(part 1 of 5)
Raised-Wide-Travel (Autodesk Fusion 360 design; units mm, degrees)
parameter "FrameLength" = 640 comment "Fixed existing outer length"
parameter "FrameWidth" = 190 comment "Fixed existing outer width"
parameter "FrameHeight" = 110 comment "Fixed existing height"
parameter "PivotHeight" = 30 comment "Above frame center"
parameter "LeverTravel" = 116 comment "Stable endpoint to endpoint"
parameter "PrintClearance" = 0.3 comment "Prototype diametral running clearance"
base_mesh_feature "Base Mesh Feature"
ground "Pin1"
work_plane "WorkPlane1" AlongDistance -36 ExtraOffset 0
sketch "Flat load-bearing plate" plane through (-36, 0, 0) normal (1, 0, 0) x axis (0, 0, -1)
  line L1 (-33, -55) -> (-33, -75)
  line L2 (2, -55) -> (-33, -55)
  line L3 (2, 55) -> (2, -55)
  line L4 (-33, 55) -> (2, 55)
  line L5 (-33, 75) -> (-33, 55)
  line L6 (-57, 75) -> (-33, 75)
  line L7 (-57, 32) -> (-57, 75)
  line L8 (-86, 26) -> (-57, 32)
  line L9 (-86, -26) -> (-86, 26)
  line L10 (-57, -32) -> (-86, -26)
  line L11 (-57, -75) -> (-57, -32)
  line L12 (-33, -75) -> (-57, -75)
extrude "Extrude1" new body sketch "Flat load-bearing plate" along normal blind 12
work_plane "WorkPlane2" AlongDistance -37 ExtraOffset 0
sketch "Replaceable bushing seat" plane through (-37, 0, 0) normal (1, 0, 0) x axis (0, 0, -1)
  circle C1 centre (-65, 0) radius 10.15
extrude "Extrude2" cut sketch "Replaceable bushing seat" along normal blind 14
work_plane "WorkPlane3" AlongDistance -37 ExtraOffset 0
sketch "Follower pivot bolt" plane through (-37, 0, 0) normal (1, 0, 0) x axis (0, 0, -1)
  circle C1 centre (-12, -35) radius 2.7
extrude "Extrude3" cut sketch "Follower pivot bolt" along normal blind 14
work_plane "WorkPlane4" AlongDistance -76 ExtraOffset 0
sketch "M5 rail mounting bore" plane through (0, -76, 0) normal (0, 1, 0) x axis (1, 0, 0)
  circle C1 centre (-30, -45) radius 2.7
extrude "Extrude4" cut sketch "M5 rail mounting bore" along normal blind 22
work_plane "WorkPlane5" AlongDistance -55 ExtraOffset 0
sketch "Rail screw tool and washer access" plane through (0, -55, 0) normal (0, 1, 0) x axis (1, 0, 0)
  circle C1 centre (-30, -45) radius 5.3
extrude "Extrude5" cut sketch "Rail screw tool and washer access" along normal blind 12
work_plane "WorkPlane6" AlongDistance 54 ExtraOffset 0
sketch "M5 rail mounting bore (1)" plane through (0, 54, 0) normal (0, 1, 0) x axis (1, 0, 0)
  circle C1 centre (-30, -45) radius 2.7
extrude "Extrude6" cut sketch "M5 rail mounting bore (1)" along normal blind 22
work_plane "WorkPlane7" AlongDistance 43 ExtraOffset 0
sketch "Rail screw tool and washer access (1)" plane through (0, 43, 0) normal (0, 1, 0) x axis (1, 0, 0)
  circle C1 centre (-30, -45) radius 5.3
extrude "Extrude7" cut sketch "Rail screw tool and washer access (1)" along normal blind 12
work_plane "WorkPlane8" AlongDistance -37 ExtraOffset 0
sketch "Spring crossblock attachment" plane through (-37, 0, 0) normal (1, 0, 0) x axis (0, 0, -1)
  circle C1 centre (-44, -59) radius 1.7
extrude "Extrude8" cut sketch "Spring crossblock attachment" along normal blind 14
work_plane "WorkPlane9" AlongDistance -37 ExtraOffset 0
sketch "Spring crossblock attachment (1)" plane through (-37, 0, 0) normal (1, 0, 0) x axis (0, 0, -1)
  circle C1 centre (-44, -51) radius 1.7
extrude "Extrude9" cut sketch "Spring crossblock attachment (1)" along normal blind 14
work_plane "WorkPlane1" AlongDistance 24 ExtraOffset 0
sketch "Flat load-bearing plate" plane through (24, 0, 0) normal (1, 0, 0) x axis (0, 0, -1)
  line L1 (-33, -55) -> (-33, -75)
  line L2 (2, -55) -> (-33, -55)
  line L3 (2, 55) -> (2, -55)
  line L4 (-33, 55) -> (2, 55)
  line L5 (-33, 75) -> (-33, 55)
  line L6 (-57, 75) -> (-33, 75)
  line L7 (-57, 32) -> (-57, 75)
  line L8 (-86, 26) -> (-57, 32)
  line L9 (-86, -26) -> (-86, 26)
  line L10 (-57, -32) -> (-86, -26)
  line L11 (-57, -75) -> (-57, -32)
  line L12 (-33, -75) -> (-57, -75)
extrude "Extrude1" new body sketch "Flat load-bearing plate" along normal blind 12
work_plane "WorkPlane2" AlongDistance 23 ExtraOffset 0
sketch "Replaceable bushing seat" plane through (23, 0, 0) normal (1, 0, 0) x axis (0, 0, -1)
  circle C1 centre (-65, 0) radius 10.15
extrude "Extrude2" cut sketch "Replaceable bushing seat" along normal blind 14
work_plane "WorkPlane3" AlongDistance 23 ExtraOffset 0
sketch "Follower pivot bolt" plane through (23, 0, 0) normal (1, 0, 0) x axis (0, 0, -1)
  circle C1 centre (-12, -35) radius 2.7
extrude "Extrude3" cut sketch "Follower pivot bolt" along normal blind 14
work_plane "WorkPlane4" AlongDistance -76 ExtraOffset 0
sketch "M5 rail mounting bore" plane through (0, -76, 0) normal (0, 1, 0) x axis (1, 0, 0)
  circle C1 centre (30, -45) radius 2.7
extrude "Extrude4" cut sketch "M5 rail mounting bore" along normal blind 22
work_plane "WorkPlane5" AlongDistance -55 ExtraOffset 0
sketch "Rail screw tool and washer access" plane through (0, -55, 0) normal (0, 1, 0) x axis (1, 0, 0)
  circle C1 centre (30, -45) radius 5.3
extrude "Extrude5" cut sketch "Rail screw tool and washer access" along normal blind 12
work_plane "WorkPlane6" AlongDistance 54 ExtraOffset 0
sketch "M5 rail mounting bore (1)" plane through (0, 54, 0) normal (0, 1, 0) x axis (1, 0, 0)
  circle C1 centre (30, -45) radius 2.7
extrude "Extrude6" cut sketch "M5 rail mounting bore (1)" along normal blind 22
work_plane "WorkPlane7" AlongDistance 43 ExtraOffset 0
sketch "Rail screw tool and washer access (1)" plane through (0, 43, 0) normal (0, 1, 0) x axis (1, 0, 0)
  circle C1 centre (30, -45) radius 5.3
extrude "Extrude7" cut sketch "Rail screw tool and washer access (1)" along normal blind 12
work_plane "WorkPlane8" AlongDistance 23 ExtraOffset 0
sketch "Spring crossblock attachment" plane through (23, 0, 0) normal (1, 0, 0) x axis (0, 0, -1)
  circle C1 centre (-44, -59) radius 1.7
extrude "Extrude8" cut sketch "Spring crossblock attachment" along normal blind 14
work_plane "WorkPlane9" AlongDistance 23 ExtraOffset 0
sketch "Spring crossblock attachment (1)" plane through (23, 0, 0) normal (1, 0, 0) x axis (0, 0, -1)
  circle C1 centre (-44, -51) radius 1.7
extrude "Extrude9" cut sketch "Spring crossblock attachment (1)" along normal blind 14
work_plane "WorkPlane1" AlongDistance -36 ExtraOffset 0
sketch "Replaceable journal body" plane through (-36, 0, 0) normal (1, 0, 0) x axis (0, 0, -1)
  circle C1 centre (-65, 0) radius 10.05
extrude "Extrude1" new body sketch "Replaceable journal body" along normal blind 12 bodies "P03 Left flanged journal bush"
work_plane "WorkPlane2" AlongDistance -37.2 ExtraOffset 0
sketch "Axial thrust flange" plane through (-37.2, 0, 0) normal (1, 0, 0) x axis (0, 0, -1)
  circle C1 centre (-65, 0) radius 12.75
extrude "Extrude2" add sketch "Axial thrust flange" along normal blind 1.2
work_plane "WorkPlane3" AlongDistance -38 ExtraOffset 0
sketch "Running journal bore" plane through (-38, 0, 0) normal (1, 0, 0) x axis (0, 0, -1)
  circle C1 centre (-65, 0) radius 6.15
extrude "Extrude3" cut sketch "Running journal bore" along normal blind 15
work_plane "WorkPlane1" AlongDistance 24 ExtraOffset 0
sketch "Replaceable journal body" plane through (24, 0, 0) normal (1, 0, 0) x axis (0, 0, -1)
  circle C1 centre (-65, 0) radius 10.05
extrude "Extrude1" new body sketch "Replaceable journal body" along normal blind 12 bodies "P04 Right flanged journal bush"
work_plane "WorkPlane2" AlongDistance 36 ExtraOffset 0
sketch "Axial thrust flange" plane through (36, 0, 0) normal (1, 0, 0) x axis (0, 0, -1)
  circle C1 centre (-65, 0) radius 12.75
extrude "Extrude2" add sketch "Axial thrust flange" along normal blind 1.2
work_plane "WorkPlane3" AlongDistance 23 ExtraOffset 0
sketch "Running journal bore" plane through (23, 0, 0) normal (1, 0, 0) x axis (0, 0, -1)
  circle C1 centre (-65, 0) radius 6.15
extrude "Extrude3" cut sketch "Running journal bore" along normal blind 15
work_plane "WorkPlane1" AlongDistance -39.35 ExtraOffset 0
sketch "Axial cap" plane through (-39.35, 0, 0) normal (1, 0, 0) x axis (0, 0, -1)
  circle C1 centre (-65, 0) radius 10
extrude "Extrude1" new body sketch "Axial cap" along normal blind 2 bodies "P06 Shaft retaining cap"
work_plane "WorkPlane2" AlongDistance -39.5 ExtraOffset 0
sketch "M3 cap screw" plane through (-39.5, 0, 0) normal (1, 0, 0) x axis (0, 0, -1)
  circle C1 centre (-65, 0) radius 1.7
extrude "Extrude2" cut sketch "M3 cap screw" along normal blind 2.4
work_plane "WorkPlane1" AlongDistance -7 ExtraOffset 0
sketch "Main lever hub" plane through (-7, 0, 0) normal (1, 0, 0) x axis (0, 0, -1)
  circle C1 centre (-65, 0) radius 22
extrude "Extrude1" new body sketch "Main lever hub" along normal blind 14 bodies "P07 Integral lever rotor and cam carrier"
work_plane "WorkPlane2" AlongDistance -7 ExtraOffset 0
sketch "Continuous reinforced lever stem" plane through (-7, 0, 0) normal (1, 0, 0) x axis (0, 0, -1)
  line L1 (-60, 14) -> (-60, -14)
  line L2 (-95, 11) -> (-60, 14)
  line L3 (-150, 7) -> (-95, 11)
  line L4 (-195, 7) -> (-150, 7)
  line L5 (-195, -7) -> (-195, 7)
  line L6 (-150, -7) -> (-195, -7)
  line L7 (-95, -11) -> (-150, -7)
  line L8 (-60, -14) -> (-95, -11)
extrude "Extrude2" add sketch "Continuous reinforced lever stem" along normal blind 14
work_plane "WorkPlane3" AlongDistance -7 ExtraOffset 0
sketch "Integrated cam carrier fan" plane through (-7, 0, 0) normal (1, 0, 0) x axis (0, 0, -1)
  line L1 (-44.5, 35.507) -> (-65, 0)
  line L2 (-42.6698, 34.3855) -> (-44.5, 35.507)
  line L3 (-40.9008, 33.1697) -> (-42.6698, 34.3855)
  line L4 (-39.1979, 31.863) -> (-40.9008, 33.1697)
  line L5 (-37.5656, 30.4689) -> (-39.1979, 31.863)
  line L6 (-36.0086, 28.9914) -> (-37.5656, 30.4689)
  line L7 (-34.5311, 27.4344) -> (-36.0086, 28.9914)
  line L8 (-33.137, 25.8021) -> (-34.5311, 27.4344)
  line L9 (-31.8303, 24.0992) -> (-33.137, 25.8021)
  line L10 (-30.6145, 22.3302) -> (-31.8303, 24.0992)
  line L11 (-29.493, 20.5) -> (-30.6145, 22.3302)
  line L12 (-28.4687, 18.6136) -> (-29.493, 20.5)
  line L13 (-27.5446, 16.6762) -> (-28.4687, 18.6136)
  line L14 (-26.7232, 14.6931) -> (-27.5446, 16.6762)
  line L15 (-26.0067, 12.6697) -> (-26.7232, 14.6931)
  line L16 (-25.397, 10.6116) -> (-26.0067, 12.6697)
  line L17 (-24.8959, 8.5244) -> (-25.397, 10.6116)
  line L18 (-24.5048, 6.4138) -> (-24.8959, 8.5244)
  line L19 (-24.2246, 4.2857) -> (-24.5048, 6.4138)
  line L20 (-24.0562, 2.1458) -> (-24.2246, 4.2857)
  line L21 (-24, 0) -> (-24.0562, 2.1458)
  line L22 (-24.0562, -2.1458) -> (-24, 0)
  line L23 (-24.2246, -4.2857) -> (-24.0562, -2.1458)
  line L24 (-24.5048, -6.4138) -> (-24.2246, -4.2857)
  line L25 (-24.8959, -8.5244) -> (-24.5048, -6.4138)
  line L26 (-25.397, -10.6116) -> (-24.8959, -8.5244)
  line L27 (-26.0067, -12.6697) -> (-25.397, -10.6116)
  line L28 (-26.7232, -14.6931) -> (-26.0067, -12.6697)
  line L29 (-27.5446, -16.6762) -> (-26.7232, -14.6931)
  line L30 (-28.4687, -18.6136) -> (-27.5446, -16.6762)
  line L31 (-29.493, -20.5) -> (-28.4687, -18.6136)
  line L32 (-30.6145, -22.3302) -> (-29.493, -20.5)
  line L33 (-31.8303, -24.0992) -> (-30.6145, -22.3302)
  line L34 (-33.137, -25.8021) -> (-31.8303, -24.0992)
  line L35 (-34.5311, -27.4344) -> (-33.137, -25.8021)
  line L36 (-36.0086, -28.9914) -> (-34.5311, -27.4344)
  line L37 (-37.5656, -30.4689) -> (-36.0086, -28.9914)
  line L38 (-39.1979, -31.863) -> (-37.5656, -30.4689)
  line L39 (-40.9008, -33.1697) -> (-39.1979, -31.863)
  line L40 (-42.6698, -34.3855) -> (-40.9008, -33.1697)
  line L41 (-44.5, -35.507) -> (-42.6698, -34.3855)
  line L42 (-65, 0) -> (-44.5, -35.507)
extrude "Extrude3" add sketch "Integrated cam carrier fan" along normal blind 14
work_plane "WorkPlane4" AlongDistance -23.6 ExtraOffset 0
sketch "Integral axial locating hub" plane through (-23.6, 0, 0) normal (1, 0, 0) x axis (0, 0, -1)
  circle C1 centre (-65, 0) radius 10
work_plane "WorkPlane5" AlongDistance -24 ExtraOffset 0
sketch "D shaft socket" plane through (-24, 0, 0) normal (1, 0, 0) x axis (0, 0, -1)
  line L1 (-69.6247, 6.65) -> (-60.3753, 6.65)
  arc A1 centre (-65, 0) radius 8.1 clockwise from (-60.3753, 6.65) to (-69.6247, 6.65)
extrude "Extrude5" cut sketch "D shaft socket" along normal blind 48
work_plane "WorkPlane6" AlongDistance 0.3 ExtraOffset 0
sketch "Cam M3 insert pocket" plane through (0.3, 0, 0) normal (1, 0, 0) x axis (0, 0, -1)
  circle C1 centre (-39.5442, 25.4558) radius 2
extrude "Extrude6" cut sketch "Cam M3 insert pocket" along normal blind 6.8
work_plane "WorkPlane7" AlongDistance 0.3 ExtraOffset 0
sketch "Cam M3 insert pocket (1)" plane through (0.3, 0, 0) normal (1, 0, 0) x axis (0, 0, -1)
  circle C1 centre (-29, 0) radius 2
extrude "Extrude7" cut sketch "Cam M3 insert pocket (1)" along normal blind 6.8
work_plane "WorkPlane8" AlongDistance 0.3 ExtraOffset 0
sketch "Cam M3 insert pocket (2)" plane through (0.3, 0, 0) normal (1, 0, 0) x axis (0, 0, -1)
  circle C1 centre (-39.5442, -25.4558) radius 2
extrude "Extrude8" cut sketch "Cam M3 insert pocket (2)" along normal blind 6.8
work_plane "WorkPlane9" AlongDistance -8 ExtraOffset 0
sketch "Grip through bolt" plane through (-8, 0, 0) normal (1, 0, 0) x axis (0, 0, -1)
  circle C1 centre (-180, 0) radius 1.7
extrude "Extrude9" cut sketch "Grip through bolt" along normal blind 16
work_plane "WorkPlane10" AlongDistance -8 ExtraOffset 0
sketch "Grip through bolt (1)" plane through (-8, 0, 0) normal (1, 0, 0) x axis (0, 0, -1)
  circle C1 centre (-190, 0) radius 1.7
extrude "Extrude10" cut sketch "Grip through bolt (1)" along normal blind 16
work_plane "WorkPlane1" AlongDistance 0 ExtraOffset 0
sketch "Palm grip smooth contour" plane through (0, 0, 0) normal (1, 0, 0) x axis (0, 0, -1)
  curve K1 (-225, 0) -> (-165, 12)
  line L1 (-225, 0) -> (-165, 0)
  line L2 (-165, 12) -> (-165, 0)
revolve "Revolve1" sketch "Palm grip smooth contour" AlongAngle 360 bodies "P09 Grip insert half"
work_plane "WorkPlane2" AlongDistance 0 ExtraOffset 0
sketch "Split on print bed face" plane through (0, 0, 0) normal (1, 0, 0) x axis (0, 0, -1)
  line L1 (-160, 30) -> (-160, -30)
  line L2 (-230, 30) -> (-160, 30)
  line L3 (-230, -30) -> (-230, 30)
  line L4 (-160, -30) -> (-230, -30)
extrude "Extrude1" cut sketch "Split on print bed face" along normal blind 30
work_plane "WorkPlane3" AlongDistance -7.2 ExtraOffset 0
sketch "Keyed stem socket" plane through (-7.2, 0, 0) normal (1, 0, 0) x axis (0, 0, -1)
  line L1 (-164, 7.2) -> (-164, -7.2)
  line L2 (-196, 7.2) -> (-164, 7.2)
  line L3 (-196, -7.2) -> (-196, 7.2)
  line L4 (-164, -7.2) -> (-196, -7.2)
extrude "Extrude2" cut sketch "Keyed stem socket" along normal blind 14.4
work_plane "WorkPlane4" AlongDistance -13.9 ExtraOffset 0
sketch "M3 grip heat set" plane through (-13.9, 0, 0) normal (1, 0, 0) x axis (0, 0, -1)
  circle C1 centre (-180, 0) radius 2
extrude "Extrude3" cut sketch "M3 grip heat set" along normal blind 6.8
work_plane "WorkPlane5" AlongDistance -13.9 ExtraOffset 0
sketch "M3 grip heat set (1)" plane through (-13.9, 0, 0) normal (1, 0, 0) x axis (0, 0, -1)
  circle C1 centre (-190, 0) radius 2
extrude "Extrude4" cut sketch "M3 grip heat set (1)" along normal blind 6.8
work_plane "WorkPlane1" AlongDistance 0 ExtraOffset 0
sketch "Palm grip smooth contour" plane through (0, 0, 0) normal (1, 0, 0) x axis (0, 0, -1)
  curve K1 (-225, 0) -> (-165, 12)
  line L1 (-225, 0) -> (-165, 0)
  line L2 (-165, 12) -> (-165, 0)
revolve "Revolve1" sketch "Palm grip smooth contour" AlongAngle 360 bodies "P10 Grip screw half"
work_plane "WorkPlane2" AlongDistance -30 ExtraOffset 0
sketch "Split on print bed face" plane through (-30, 0, 0) normal (1, 0, 0) x axis (0, 0, -1)
  line L1 (-160, 30) -> (-160, -30)
  line L2 (-230, 30) -> (-160, 30)
  line L3 (-230, -30) -> (-230, 30)
  line L4 (-160, -30) -> (-230, -30)
extrude "Extrude1" cut sketch "Split on print bed face" along normal blind 30
work_plane "WorkPlane3" AlongDistance -7.2 ExtraOffset 0
sketch "Keyed stem socket" plane through (-7.2, 0, 0) normal (1, 0, 0) x axis (0, 0, -1)
  line L1 (-164, 7.2) -> (-164, -7.2)
  line L2 (-196, 7.2) -> (-164, 7.2)
  line L3 (-196, -7.2) -> (-196, 7.2)
  line L4 (-164, -7.2) -> (-196, -7.2)
extrude "Extrude2" cut sketch "Keyed stem socket" along normal blind 14.4
work_plane "WorkPlane4" AlongDistance -0.1 ExtraOffset 0
sketch "Grip screw bore" plane through (-0.1, 0, 0) normal (1, 0, 0) x axis (0, 0, -1)
  circle C1 centre (-180, 0) radius 1.7
extrude "Extrude3" cut sketch "Grip screw bore" along normal blind 26
work_plane "WorkPlane5" AlongDistance 12.5 ExtraOffset 0
sketch "Recessed grip screw head" plane through (12.5, 0, 0) normal (1, 0, 0) x axis (0, 0, -1)
  circle C1 centre (-180, 0) radius 3.1
extrude "Extrude4" cut sketch "Recessed grip screw head" along normal blind 14
work_plane "WorkPlane6" AlongDistance -0.1 ExtraOffset 0
sketch "Grip screw bore (1)" plane through (-0.1, 0, 0) normal (1, 0, 0) x axis (0, 0, -1)
  circle C1 centre (-190, 0) radius 1.7
extrude "Extrude5" cut sketch "Grip screw bore (1)" along normal blind 26
work_plane "WorkPlane7" AlongDistance 12.5 ExtraOffset 0
sketch "Recessed grip screw head (1)" plane through (12.5, 0, 0) normal (1, 0, 0) x axis (0, 0, -1)
  circle C1 centre (-190, 0) radius 3.1
extrude "Extrude6" cut sketch "Recessed grip screw head (1)" along normal blind 14
work_plane "WorkPlane1" AlongDistance 4 ExtraOffset 0
sketch "First strong flat cheek" plane through (4, 0, 0) normal (1, 0, 0) x axis (0, 0, -1)
  line L1 (-6, -5) -> (-6, -61)
  line L2 (-7, 0) -> (-6, -5)
  line L3 (-17, 0) -> (-7, 0)
  line L4 (-18, -5) -> (-17, 0)
  line L5 (-18, -61) -> (-18, -5)
  line L6 (-6, -61) -> (-18, -61)
extrude "Extrude1" new body sketch "First strong flat cheek" along normal blind 3 bodies "P11 Forked roller follower"
work_plane "WorkPlane2" AlongDistance 4 ExtraOffset 0
sketch "Spring tail bridge" plane through (4, 0, 0) normal (1, 0, 0) x axis (0, 0, -1)
  line L1 (-6, -49) -> (-6, -61)
  line L2 (-18, -49) -> (-6, -49)
  line L3 (-18, -61) -> (-18, -49)
  line L4 (-6, -61) -> (-18, -61)
extrude "Extrude2" add sketch "Spring tail bridge" along normal blind 16
work_plane "WorkPlane3" AlongDistance 17 ExtraOffset 0
sketch "Second supporting cheek" plane through (17, 0, 0) normal (1, 0, 0) x axis (0, 0, -1)
  line L1 (-6, -5) -> (-6, -61)
  line L2 (-7, 0) -> (-6, -5)
  line L3 (-17, 0) -> (-7, 0)
  line L4 (-18, -5) -> (-17, 0)
  line L5 (-18, -61) -> (-18, -5)
  line L6 (-6, -61) -> (-18, -61)
extrude "Extrude3" add sketch "Second supporting cheek" along normal blind 3
work_plane "WorkPlane4" AlongDistance 4 ExtraOffset 0
sketch "Rounded roller cheek" plane through (4, 0, 0) normal (1, 0, 0) x axis (0, 0, -1)
  circle C1 centre (-12, 0) radius 6
extrude "Extrude4" add sketch "Rounded roller cheek" along normal blind 3
work_plane "WorkPlane5" AlongDistance 17 ExtraOffset 0
sketch "Rounded roller cheek (1)" plane through (17, 0, 0) normal (1, 0, 0) x axis (0, 0, -1)
  circle C1 centre (-12, 0) radius 6
extrude "Extrude5" add sketch "Rounded roller cheek (1)" along normal blind 3
work_plane "WorkPlane6" AlongDistance 3.9 ExtraOffset 0
sketch "Smooth pivot sleeve bore" plane through (3.9, 0, 0) normal (1, 0, 0) x axis (0, 0, -1)
  circle C1 centre (-12, -35) radius 4.15
extrude "Extrude6" cut sketch "Smooth pivot sleeve bore" along normal blind 16.2
work_plane "WorkPlane7" AlongDistance 3.9 ExtraOffset 0
sketch "Roller axle holes" plane through (3.9, 0, 0) normal (1, 0, 0) x axis (0, 0, -1)
  circle C1 centre (-12, 0) radius 1.7
extrude "Extrude7" cut sketch "Roller axle holes" along normal blind 16.2
work_plane "WorkPlane8" AlongDistance 3.9 ExtraOffset 0
sketch "Roller M3 nut recess" plane through (3.9, 0, 0) normal (1, 0, 0) x axis (0, 0, -1)
  line L1 (-14.9, 1.6743) -> (-12, 3.3486)
  line L2 (-14.9, -1.6743) -> (-14.9, 1.6743)
  line L3 (-12, -3.3486) -> (-14.9, -1.6743)
  line L4 (-9.1, -1.6743) -> (-12, -3.3486)
  line L5 (-9.1, 1.6743) -> (-9.1, -1.6743)
  line L6 (-12, 3.3486) -> (-9.1, 1.6743)
extrude "Extrude8" cut sketch "Roller M3 nut recess" along normal blind 1.6
work_plane "WorkPlane9" AlongDistance 18 ExtraOffset 0
sketch "Spring tail locating pilot" plane through (0, 0, 18) normal (0, 0, 1) x axis (1, 0, 0)
  circle C1 centre (12, -55) radius 1.8
extrude "Extrude9" add sketch "Spring tail locating pilot" along normal blind 2
work_plane "WorkPlane1" AlongDistance -24 ExtraOffset 0
sketch "Captured spring reaction block" plane through (-24, 0, 0) normal (1, 0, 0) x axis (0, 0, -1)
  line L1 (-38, -44) -> (-38, -66)
  line L2 (-52, -44) -> (-38, -44)
  line L3 (-52, -66) -> (-52, -44)
  line L4 (-38, -66) -> (-52, -66)
extrude "Extrude1" new body sketch "Captured spring reaction block" along normal blind 48
work_plane "WorkPlane2" AlongDistance -24.1 ExtraOffset 0
sketch "Left M3 insert with screw tip relief" plane through (-24.1, 0, 0) normal (1, 0, 0) x axis (0, 0, -1)
  circle C1 centre (-44, -59) radius 2
extrude "Extrude2" cut sketch "Left M3 insert with screw tip relief" along normal blind 8.8
work_plane "WorkPlane3" AlongDistance 15.3 ExtraOffset 0
sketch "Right M3 insert with screw tip relief" plane through (15.3, 0, 0) normal (1, 0, 0) x axis (0, 0, -1)
  circle C1 centre (-44, -59) radius 2
extrude "Extrude3" cut sketch "Right M3 insert with screw tip relief" along normal blind 8.8
work_plane "WorkPlane4" AlongDistance -24.1 ExtraOffset 0
sketch "Left M3 insert with screw tip relief (1)" plane through (-24.1, 0, 0) normal (1, 0, 0) x axis (0, 0, -1)
  circle C1 centre (-44, -51) radius 2
extrude "Extrude4" cut sketch "Left M3 insert with screw tip relief (1)" along normal blind 8.8
work_plane "WorkPlane5" AlongDistance 15.3 ExtraOffset 0
sketch "Right M3 insert with screw tip relief (1)" plane through (15.3, 0, 0) normal (1, 0, 0) x axis (0, 0, -1)
  circle C1 centre (-44, -51) radius 2
extrude "Extrude5" cut sketch "Right M3 insert with screw tip relief (1)" along normal blind 8.8
work_plane "WorkPlane6" AlongDistance 37.9 ExtraOffset 0
sketch "M4 preload adjuster" plane through (0, 0, 37.9) normal (0, 0, 1) x axis (1, 0, 0)
  circle C1 centre (12, -55) radius 2.2
extrude "Extrude6" cut sketch "M4 preload adjuster" along normal blind 14.2
work_plane "WorkPlane7" AlongDistance 37.9 ExtraOffset 0
sketch "Spring-side loaded retained M4 nut" plane through (0, 0, 37.9) normal (0, 0, 1) x axis (1, 0, 0)
  line L1 (14.1362, -51.3) -> (16.2724, -55)
  line L2 (9.8638, -51.3) -> (14.1362, -51.3)
  line L3 (7.7276, -55) -> (9.8638, -51.3)
  line L4 (9.8638, -58.7) -> (7.7276, -55)
  line L5 (14.1362, -58.7) -> (9.8638, -58.7)
  line L6 (16.2724, -55) -> (14.1362, -58.7)
extrude "Extrude7" cut sketch "Spring-side loaded retained M4 nut" along normal blind 3.5
work_plane "WorkPlane8" AlongDistance 37.9 ExtraOffset 0
sketch "Spring cup guide bolts" plane through (0, 0, 37.9) normal (0, 0, 1) x axis (1, 0, 0)
  circle C1 centre (5, -55) radius 1.7
extrude "Extrude8" cut sketch "Spring cup guide bolts" along normal blind 14.2
work_plane "WorkPlane9" AlongDistance 37.9 ExtraOffset 0
sketch "Spring cup guide bolts (1)" plane through (0, 0, 37.9) normal (0, 0, 1) x axis (1, 0, 0)
  circle C1 centre (19, -55) radius 1.7
extrude "Extrude9" cut sketch "Spring cup guide bolts (1)" along normal blind 14.2
work_plane "WorkPlane11" AlongDistance -18 ExtraOffset 0
sketch "Dedicated thick stop lug" plane through (-18, 0, 0) normal (1, 0, 0) x axis (0, 0, -1)
  line L1 (-72, 5) -> (-72, -5)
  line L2 (-95, 5) -> (-72, 5)
  line L3 (-95, -5) -> (-95, 5)
  line L4 (-72, -5) -> (-95, -5)
extrude "Extrude11" add sketch "Dedicated thick stop lug" along normal blind 11.5
work_plane "WorkPlane12" AlongDistance -18 ExtraOffset 0
sketch "Rounded stop contact" plane through (-18, 0, 0) normal (1, 0, 0) x axis (0, 0, -1)
  circle C1 centre (-95, 0) radius 5
extrude "Extrude12" add sketch "Rounded stop contact" along normal blind 11.5
work_plane "WorkPlane10" AlongDistance -36 ExtraOffset 0
sketch "Broad stop support ear" plane through (-36, 0, 0) normal (1, 0, 0) x axis (0, 0, -1)
  line L1 (-60, -20) -> (-60, -44)
  line L2 (-90, -20) -> (-60, -20)
  line L3 (-90, -44) -> (-90, -20)
  line L4 (-60, -44) -> (-90, -44)
extrude "Extrude10" add sketch "Broad stop support ear" along normal blind 12
work_plane "WorkPlane11" AlongDistance -24 ExtraOffset 0
sketch "Integrated steel-core end stop" plane through (-24, 0, 0) normal (1, 0, 0) x axis (0, 0, -1)
  circle C1 centre (-79.6754, -33.9652) radius 6
work_plane "WorkPlane12" AlongDistance -36.1 ExtraOffset 0
sketch "M5 stop reinforcement bolt" plane through (-36.1, 0, 0) normal (1, 0, 0) x axis (0, 0, -1)
  circle C1 centre (-79.6754, -33.9652) radius 2.7
work_plane "WorkPlane13" AlongDistance -15.4 ExtraOffset 0
sketch "M5 captive stop nut" plane through (-15.4, 0, 0) normal (1, 0, 0) x axis (0, 0, -1)
  line L1 (-83.8754, -31.5403) -> (-79.6754, -29.1154)
  line L2 (-83.8754, -36.39) -> (-83.8754, -31.5403)
  line L3 (-79.6754, -38.8149) -> (-83.8754, -36.39)
  line L4 (-75.4754, -36.39) -> (-79.6754, -38.8149)
  line L5 (-75.4754, -31.5403) -> (-75.4754, -36.39)
  line L6 (-79.6754, -29.1154) -> (-75.4754, -31.5403)
work_plane "WorkPlane14" AlongDistance -36 ExtraOffset 0
sketch "Broad stop support ear (1)" plane through (-36, 0, 0) normal (1, 0, 0) x axis (0, 0, -1)
  line L1 (-60, 44) -> (-60, 20)
  line L2 (-90, 44) -> (-60, 44)
  line L3 (-90, 20) -> (-90, 44)
  line L4 (-60, 20) -> (-90, 20)
extrude "Extrude14" add sketch "Broad stop support ear (1)" along normal blind 12
work_plane "WorkPlane15" AlongDistance -24 ExtraOffset 0
sketch "Integrated steel-core end stop (1)" plane through (-24, 0, 0) normal (1, 0, 0) x axis (0, 0, -1)
  circle C1 centre (-79.6754, 33.9652) radius 6
work_plane "WorkPlane16" AlongDistance -36.1 ExtraOffset 0
sketch "M5 stop reinforcement bolt (1)" plane through (-36.1, 0, 0) normal (1, 0, 0) x axis (0, 0, -1)
  circle C1 centre (-79.6754, 33.9652) radius 2.7
work_plane "WorkPlane17" AlongDistance -15.4 ExtraOffset 0
sketch "M5 captive stop nut (1)" plane through (-15.4, 0, 0) normal (1, 0, 0) x axis (0, 0, -1)
  line L1 (-83.8754, 36.39) -> (-79.6754, 38.8149)
  line L2 (-83.8754, 31.5403) -> (-83.8754, 36.39)
  line L3 (-79.6754, 29.1154) -> (-83.8754, 31.5403)
  line L4 (-75.4754, 31.5403) -> (-79.6754, 29.1154)
  line L5 (-75.4754, 36.39) -> (-75.4754, 31.5403)
  line L6 (-79.6754, 38.8149) -> (-75.4754, 36.39)
work_plane "WorkPlane13" AlongDistance -24 ExtraOffset 0
sketch "Restore shaft socket through stop-lug root" plane through (-24, 0, 0) normal (1, 0, 0) x axis (0, 0, -1)
  line L1 (-69.6247, 6.65) -> (-60.3753, 6.65)
  arc A1 centre (-65, 0) radius 8.1 clockwise from (-60.3753, 6.65) to (-69.6247, 6.65)
extrude "Extrude13" cut sketch "Restore shaft socket through stop-lug root" along normal blind 48
work_plane "WorkPlane10" AlongDistance -24.1 ExtraOffset 0
sketch "Cam sweep clearance through crossblock" plane through (-24.1, 0, 0) normal (1, 0, 0) x axis (0, 0, -1)
  circle C1 centre (-65, 0) radius 51
extrude "Extrude10" cut sketch "Cam sweep clearance through crossblock" along normal blind 48.2
work_plane "WorkPlane10" AlongDistance 36 ExtraOffset 0
sketch "Rigid sensor carriage support" plane through (36, 0, 0) normal (1, 0, 0) x axis (0, 0, -1)
  line L1 (-49, -18) -> (-49, -28)
  line L2 (-81, -18) -> (-49, -18)
  line L3 (-81, -28) -> (-81, -18)
  line L4 (-49, -28) -> (-81, -28)
extrude "Extrude10" add sketch "Rigid sensor carriage support" along normal blind 44
work_plane "WorkPlane11" AlongDistance -28.1 ExtraOffset 0
sketch "M3 sensor carriage heat set" plane through (0, -28.1, 0) normal (0, 1, 0) x axis (1, 0, 0)
  circle C1 centre (74, -65) radius 2
extrude "Extrude11" cut sketch "M3 sensor carriage heat set" along normal blind 6.8
work_plane "WorkPlane12" AlongDistance 36 ExtraOffset 0
sketch "Rigid sensor carriage support (1)" plane through (36, 0, 0) normal (1, 0, 0) x axis (0, 0, -1)
  line L1 (-49, 28) -> (-49, 18)
  line L2 (-81, 28) -> (-49, 28)
  line L3 (-81, 18) -> (-81, 28)
  line L4 (-49, 18) -> (-81, 18)
extrude "Extrude12" add sketch "Rigid sensor carriage support (1)" along normal blind 44
work_plane "WorkPlane13" AlongDistance 21.3 ExtraOffset 0
sketch "M3 sensor carriage heat set (1)" plane through (0, 21.3, 0) normal (0, 1, 0) x axis (1, 0, 0)
  circle C1 centre (74, -65) radius 2
extrude "Extrude13" cut sketch "M3 sensor carriage heat set (1)" along normal blind 6.8
work_plane "WorkPlane1" AlongDistance -24 ExtraOffset 0
sketch "Controlled follower end float" plane through (-24, 0, 0) normal (1, 0, 0) x axis (0, 0, -1)
  circle C1 centre (-12, -35) radius 6
extrude "Extrude1" new body sketch "Controlled follower end float" along normal blind 27.8 bodies "P21 Follower left axial spacer"
work_plane "WorkPlane2" AlongDistance -24.1 ExtraOffset 0
sketch "Pivot sleeve running clearance" plane through (-24.1, 0, 0) normal (1, 0, 0) x axis (0, 0, -1)
  circle C1 centre (-12, -35) radius 4.2
extrude "Extrude2" cut sketch "Pivot sleeve running clearance" along normal blind 28
work_plane "WorkPlane1" AlongDistance 20.2 ExtraOffset 0
sketch "Controlled follower end float" plane through (20.2, 0, 0) normal (1, 0, 0) x axis (0, 0, -1)
  circle C1 centre (-12, -35) radius 6
extrude "Extrude1" new body sketch "Controlled follower end float" along normal blind 3.8 bodies "P22 Follower right axial spacer"
work_plane "WorkPlane2" AlongDistance 20.1 ExtraOffset 0
sketch "Pivot sleeve running clearance" plane through (20.1, 0, 0) normal (1, 0, 0) x axis (0, 0, -1)
  circle C1 centre (-12, -35) radius 4.2
extrude "Extrude2" cut sketch "Pivot sleeve running clearance" along normal blind 4
work_plane "WorkPlane1" AlongDistance 3.1 ExtraOffset 0
sketch "Roller axle M3 nut" plane through (3.1, 0, 0) normal (1, 0, 0) x axis (0, 0, -1)
  line L1 (-14.75, 1.5877) -> (-12, 3.1754)
  line L2 (-14.75, -1.5877) -> (-14.75, 1.5877)
  line L3 (-12, -3.1754) -> (-14.75, -1.5877)
  line L4 (-9.25, -1.5877) -> (-12, -3.1754)
  line L5 (-9.25, 1.5877) -> (-9.25, -1.5877)
  line L6 (-12, 3.1754) -> (-9.25, 1.5877)
extrude "Extrude1" new body sketch "Roller axle M3 nut" along normal blind 2.4 bodies "HARDWARE Roller axle M3 nut"
work_plane "WorkPlane2" AlongDistance 3 ExtraOffset 0
sketch "Thread envelope" plane through (3, 0, 0) normal (1, 0, 0) x axis (0, 0, -1)
  circle C1 centre (-12, 0) radius 1.5
extrude "Extrude2" cut sketch "Thread envelope" along normal blind 2.6
work_plane "WorkPlane14" AlongDistance 23.9 ExtraOffset 0
sketch "Cam lateral service opening" plane through (23.9, 0, 0) normal (1, 0, 0) x axis (0, 0, -1)
  line L1 (-42.2047, 46.7373) -> (-43.8497, 47.5044)
  line L2 (-40.5875, 45.9133) -> (-42.2047, 46.7373)
  line L3 (-39, 45.0333) -> (-40.5875, 45.9133)
  line L4 (-37.4442, 44.0985) -> (-39, 45.0333)
  line L5 (-35.922, 43.11) -> (-37.4442, 44.0985)
  line L6 (-34.4352, 42.0689) -> (-35.922, 43.11)
  line L7 (-32.9856, 40.9766) -> (-34.4352, 42.0689)
  line L8 (-31.575, 39.8343) -> (-32.9856, 40.9766)
  line L9 (-30.2052, 38.6435) -> (-31.575, 39.8343)
  line L10 (-28.8778, 37.4057) -> (-30.2052, 38.6435)
  line L11 (-27.5943, 36.1222) -> (-28.8778, 37.4057)
  line L12 (-26.3565, 34.7948) -> (-27.5943, 36.1222)
  line L13 (-25.1657, 33.425) -> (-26.3565, 34.7948)
  line L14 (-24.0234, 32.0144) -> (-25.1657, 33.425)
  line L15 (-22.9311, 30.5648) -> (-24.0234, 32.0144)
  line L16 (-21.89, 29.078) -> (-22.9311, 30.5648)
  line L17 (-20.9015, 27.5558) -> (-21.89, 29.078)
  line L18 (-19.9667, 26) -> (-20.9015, 27.5558)
  line L19 (-19.0867, 24.4125) -> (-19.9667, 26)
  line L20 (-18.2627, 22.7953) -> (-19.0867, 24.4125)
  line L21 (-17.4956, 21.1503) -> (-18.2627, 22.7953)
  line L22 (-16.7864, 19.4795) -> (-17.4956, 21.1503)
  line L23 (-16.136, 17.785) -> (-16.7864, 19.4795)
  line L24 (-15.5451, 16.0689) -> (-16.136, 17.785)
  line L25 (-15.0144, 14.3331) -> (-15.5451, 16.0689)
  line L26 (-14.5446, 12.5799) -> (-15.0144, 14.3331)
  line L27 (-14.1363, 10.8114) -> (-14.5446, 12.5799)
  line L28 (-13.79, 9.0297) -> (-14.1363, 10.8114)
  line L29 (-13.5061, 7.237) -> (-13.79, 9.0297)
  line L30 (-13.2849, 5.4355) -> (-13.5061, 7.237)
  line L31 (-13.1267, 3.6273) -> (-13.2849, 5.4355)
  line L32 (-13.0317, 1.8148) -> (-13.1267, 3.6273)
  line L33 (-13, 0) -> (-13.0317, 1.8148)
  line L34 (-13.0317, -1.8148) -> (-13, 0)
  line L35 (-13.1267, -3.6273) -> (-13.0317, -1.8148)
  line L36 (-13.2849, -5.4355) -> (-13.1267, -3.6273)
  line L37 (-13.5061, -7.237) -> (-13.2849, -5.4355)
  line L38 (-13.79, -9.0297) -> (-13.5061, -7.237)
  line L39 (-14.1363, -10.8114) -> (-13.79, -9.0297)
  line L40 (-14.5446, -12.5799) -> (-14.1363, -10.8114)
  line L41 (-15.0144, -14.3331) -> (-14.5446, -12.5799)
  line L42 (-15.5451, -16.0689) -> (-15.0144, -14.3331)
  line L43 (-16.136, -17.785) -> (-15.5451, -16.0689)
  line L44 (-16.7864, -19.4795) -> (-16.136, -17.785)
  line L45 (-17.4956, -21.1503) -> (-16.7864, -19.4795)
  line L46 (-18.2627, -22.7953) -> (-17.4956, -21.1503)
  line L47 (-19.0867, -24.4125) -> (-18.2627, -22.7953)
  line L48 (-19.9667, -26) -> (-19.0867, -24.4125)
  line L49 (-20.9015, -27.5558) -> (-19.9667, -26)
  line L50 (-21.89, -29.078) -> (-20.9015, -27.5558)
  line L51 (-22.9311, -30.5648) -> (-21.89, -29.078)
  line L52 (-24.0234, -32.0144) -> (-22.9311, -30.5648)
  line L53 (-25.1657, -33.425) -> (-24.0234, -32.0144)
  line L54 (-26.3565, -34.7948) -> (-25.1657, -33.425)
  line L55 (-27.5943, -36.1222) -> (-26.3565, -34.7948)
  line L56 (-28.8778, -37.4057) -> (-27.5943, -36.1222)
  line L57 (-30.2052, -38.6435) -> (-28.8778, -37.4057)
  line L58 (-31.575, -39.8343) -> (-30.2052, -38.6435)
  line L59 (-32.9856, -40.9766) -> (-31.575, -39.8343)
  line L60 (-34.4352, -42.0689) -> (-32.9856, -40.9766)
  line L61 (-35.922, -43.11) -> (-34.4352, -42.0689)
  line L62 (-37.4442, -44.0985) -> (-35.922, -43.11)
  line L63 (-39, -45.0333) -> (-37.4442, -44.0985)
  line L64 (-40.5875, -45.9133) -> (-39, -45.0333)
  line L65 (-42.2047, -46.7373) -> (-40.5875, -45.9133)
  line L66 (-43.8497, -47.5044) -> (-42.2047, -46.7373)
  line L67 (-54.4248, -23.7522) -> (-43.8497, -47.5044)
  line L68 (-53.6024, -23.3686) -> (-54.4248, -23.7522)
  line L69 (-52.7937, -22.9566) -> (-53.6024, -23.3686)
  line L70 (-52, -22.5167) -> (-52.7937, -22.9566)
  line L71 (-51.2221, -22.0493) -> (-52, -22.5167)
  line L72 (-50.461, -21.555) -> (-51.2221, -22.0493)
  line L73 (-49.7176, -21.0344) -> (-50.461, -21.555)
  line L74 (-48.9928, -20.4883) -> (-49.7176, -21.0344)
  line L75 (-48.2875, -19.9172) -> (-48.9928, -20.4883)
  line L76 (-47.6026, -19.3218) -> (-48.2875, -19.9172)
  line L77 (-46.9389, -18.7028) -> (-47.6026, -19.3218)
  line L78 (-46.2972, -18.0611) -> (-46.9389, -18.7028)
  line L79 (-45.6782, -17.3974) -> (-46.2972, -18.0611)
  line L80 (-45.0828, -16.7125) -> (-45.6782, -17.3974)
  line L81 (-44.5117, -16.0072) -> (-45.0828, -16.7125)
  line L82 (-43.9656, -15.2824) -> (-44.5117, -16.0072)
  line L83 (-43.445, -14.539) -> (-43.9656, -15.2824)
  line L84 (-42.9507, -13.7779) -> (-43.445, -14.539)
  line L85 (-42.4833, -13) -> (-42.9507, -13.7779)
  line L86 (-42.0434, -12.2063) -> (-42.4833, -13)
  line L87 (-41.6314, -11.3976) -> (-42.0434, -12.2063)
  line L88 (-41.2478, -10.5752) -> (-41.6314, -11.3976)
  line L89 (-40.8932, -9.7398) -> (-41.2478, -10.5752)
  line L90 (-40.568, -8.8925) -> (-40.8932, -9.7398)
  line L91 (-40.2725, -8.0344) -> (-40.568, -8.8925)
  line L92 (-40.0072, -7.1666) -> (-40.2725, -8.0344)
  line L93 (-39.7723, -6.29) -> (-40.0072, -7.1666)
  line L94 (-39.5682, -5.4057) -> (-39.7723, -6.29)
  line L95 (-39.395, -4.5149) -> (-39.5682, -5.4057)
  line L96 (-39.253, -3.6185) -> (-39.395, -4.5149)
  line L97 (-39.1424, -2.7177) -> (-39.253, -3.6185)
  line L98 (-39.0633, -1.8137) -> (-39.1424, -2.7177)
  line L99 (-39.0158, -0.9074) -> (-39.0633, -1.8137)
  line L100 (-39, 0) -> (-39.0158, -0.9074)
  line L101 (-39.0158, 0.9074) -> (-39, 0)
  line L102 (-39.0633, 1.8137) -> (-39.0158, 0.9074)
  line L103 (-39.1424, 2.7177) -> (-39.0633, 1.8137)
  line L104 (-39.253, 3.6185) -> (-39.1424, 2.7177)
  line L105 (-39.395, 4.5149) -> (-39.253, 3.6185)
  line L106 (-39.5682, 5.4057) -> (-39.395, 4.5149)
  line L107 (-39.7723, 6.29) -> (-39.5682, 5.4057)
  line L108 (-40.0072, 7.1666) -> (-39.7723, 6.29)
  line L109 (-40.2725, 8.0344) -> (-40.0072, 7.1666)
  line L110 (-40.568, 8.8925) -> (-40.2725, 8.0344)
  line L111 (-40.8932, 9.7398) -> (-40.568, 8.8925)
  line L112 (-41.2478, 10.5752) -> (-40.8932, 9.7398)
  line L113 (-41.6314, 11.3976) -> (-41.2478, 10.5752)
  line L114 (-42.0434, 12.2063) -> (-41.6314, 11.3976)
  line L115 (-42.4833, 13) -> (-42.0434, 12.2063)
  line L116 (-42.9507, 13.7779) -> (-42.4833, 13)
  line L117 (-43.445, 14.539) -> (-42.9507, 13.7779)
  line L118 (-43.9656, 15.2824) -> (-43.445, 14.539)
  line L119 (-44.5117, 16.0072) -> (-43.9656, 15.2824)
  line L120 (-45.0828, 16.7125) -> (-44.5117, 16.0072)
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extrude "Extrude14" cut sketch "Cam lateral service opening" along normal blind 12.2
work_plane "WorkPlane15" AlongDistance 36 ExtraOffset 0
sketch "Clear service path beneath sensor rails" plane through (36, 0, 0) normal (1, 0, 0) x axis (0, 0, -1)
  line L1 (-48.9, -18) -> (-48.9, -28)
  line L2 (-56, -18) -> (-48.9, -18)
  line L3 (-56, -28) -> (-56, -18)
  line L4 (-48.9, -28) -> (-56, -28)
extrude "Extrude15" cut sketch "Clear service path beneath sensor rails" along normal blind 44.1
work_plane "WorkPlane16" AlongDistance 36 ExtraOffset 0
sketch "Clear service path beneath sensor rails (1)" plane through (36, 0, 0) normal (1, 0, 0) x axis (0, 0, -1)
  line L1 (-48.9, 28) -> (-48.9, 18)
  line L2 (-56, 28) -> (-48.9, 28)
  line L3 (-56, 18) -> (-56, 28)
  line L4 (-48.9, 18) -> (-56, 18)
extrude "Extrude16" cut sketch "Clear service path beneath sensor rails (1)" along normal blind 44.1
work_plane "WorkPlane11" AlongDistance -24 ExtraOffset 0
sketch "Raise mount clear of rail bolt axes" plane through (-24, 0, 0) normal (1, 0, 0) x axis (0, 0, -1)
  line L1 (-52, -44) -> (-52, -66)
  line L2 (-57, -44) -> (-52, -44)
  line L3 (-57, -66) -> (-57, -44)
  line L4 (-52, -66) -> (-57, -66)
extrude "Extrude11" add sketch "Raise mount clear of rail bolt axes" along normal blind 48
work_plane "WorkPlane12" AlongDistance -24 ExtraOffset 0
sketch "Close old block mounting hole" plane through (-24, 0, 0) normal (1, 0, 0) x axis (0, 0, -1)
  circle C1 centre (-44, -59) radius 2.01
extrude "Extrude12" add sketch "Close old block mounting hole" along normal blind 8.7
work_plane "WorkPlane13" AlongDistance -24.1 ExtraOffset 0
sketch "Raised M3 block insert" plane through (-24.1, 0, 0) normal (1, 0, 0) x axis (0, 0, -1)
  circle C1 centre (-52, -59) radius 2
extrude "Extrude13" cut sketch "Raised M3 block insert" along normal blind 8.9
work_plane "WorkPlane14" AlongDistance 15.3 ExtraOffset 0
sketch "Close old block mounting hole (1)" plane through (15.3, 0, 0) normal (1, 0, 0) x axis (0, 0, -1)
  circle C1 centre (-44, -59) radius 2.01
extrude "Extrude14" add sketch "Close old block mounting hole (1)" along normal blind 8.7
work_plane "WorkPlane15" AlongDistance 15.2 ExtraOffset 0
sketch "Raised M3 block insert (1)" plane through (15.2, 0, 0) normal (1, 0, 0) x axis (0, 0, -1)
  circle C1 centre (-52, -59) radius 2
extrude "Extrude15" cut sketch "Raised M3 block insert (1)" along normal blind 8.9
work_plane "WorkPlane18" AlongDistance -36 ExtraOffset 0
sketch "Close old plate mounting hole" plane through (-36, 0, 0) normal (1, 0, 0) x axis (0, 0, -1)
  circle C1 centre (-44, -59) radius 1.71
extrude "Extrude18" add sketch "Close old plate mounting hole" along normal blind 12
work_plane "WorkPlane19" AlongDistance -36.1 ExtraOffset 0
sketch "Raised M3 block fastener" plane through (-36.1, 0, 0) normal (1, 0, 0) x axis (0, 0, -1)
  circle C1 centre (-52, -59) radius 1.7
extrude "Extrude19" cut sketch "Raised M3 block fastener" along normal blind 12.2
work_plane "WorkPlane17" AlongDistance 24 ExtraOffset 0
sketch "Close old plate mounting hole" plane through (24, 0, 0) normal (1, 0, 0) x axis (0, 0, -1)
  circle C1 centre (-44, -59) radius 1.71
extrude "Extrude17" add sketch "Close old plate mounting hole" along normal blind 12
work_plane "WorkPlane18" AlongDistance 23.9 ExtraOffset 0
sketch "Raised M3 block fastener" plane through (23.9, 0, 0) normal (1, 0, 0) x axis (0, 0, -1)
  circle C1 centre (-52, -59) radius 1.7
extrude "Extrude18" cut sketch "Raised M3 block fastener" along normal blind 12.2
work_plane "WorkPlane16" AlongDistance -24 ExtraOffset 0
sketch "Close old block mounting hole (2)" plane through (-24, 0, 0) normal (1, 0, 0) x axis (0, 0, -1)
  circle C1 centre (-44, -51) radius 2.01
extrude "Extrude16" add sketch "Close old block mounting hole (2)" along normal blind 8.7
work_plane "WorkPlane17" AlongDistance -24.1 ExtraOffset 0
sketch "Raised M3 block insert (2)" plane through (-24.1, 0, 0) normal (1, 0, 0) x axis (0, 0, -1)
  circle C1 centre (-52, -51) radius 2
extrude "Extrude17" cut sketch "Raised M3 block insert (2)" along normal blind 8.9
work_plane "WorkPlane18" AlongDistance 15.3 ExtraOffset 0
sketch "Close old block mounting hole (3)" plane through (15.3, 0, 0) normal (1, 0, 0) x axis (0, 0, -1)
  circle C1 centre (-44, -51) radius 2.01
extrude "Extrude18" add sketch "Close old block mounting hole (3)" along normal blind 8.7
work_plane "WorkPlane19" AlongDistance 15.2 ExtraOffset 0
sketch "Raised M3 block insert (3)" plane through (15.2, 0, 0) normal (1, 0, 0) x axis (0, 0, -1)
  circle C1 centre (-52, -51) radius 2
extrude "Extrude19" cut sketch "Raised M3 block insert (3)" along normal blind 8.9
work_plane "WorkPlane20" AlongDistance -36 ExtraOffset 0
sketch "Close old plate mounting hole (1)" plane through (-36, 0, 0) normal (1, 0, 0) x axis (0, 0, -1)
  circle C1 centre (-44, -51) radius 1.71
extrude "Extrude20" add sketch "Close old plate mounting hole (1)" along normal blind 12
work_plane "WorkPlane21" AlongDistance -36.1 ExtraOffset 0
sketch "Raised M3 block fastener (1)" plane through (-36.1, 0, 0) normal (1, 0, 0) x axis (0, 0, -1)
  circle C1 centre (-52, -51) radius 1.7
extrude "Extrude21" cut sketch "Raised M3 block fastener (1)" along normal blind 12.2
work_plane "WorkPlane19" AlongDistance 24 ExtraOffset 0
sketch "Close old plate mounting hole (1)" plane through (24, 0, 0) normal (1, 0, 0) x axis (0, 0, -1)
  circle C1 centre (-44, -51) radius 1.71
extrude "Extrude19" add sketch "Close old plate mounting hole (1)" along normal blind 12
work_plane "WorkPlane20" AlongDistance 23.9 ExtraOffset 0
sketch "Raised M3 block fastener (1)" plane through (23.9, 0, 0) normal (1, 0, 0) x axis (0, 0, -1)
  circle C1 centre (-52, -51) radius 1.7
extrude "Extrude20" cut sketch "Raised M3 block fastener (1)" along normal blind 12.2
work_plane "WorkPlane20" AlongDistance 51.9 ExtraOffset 0
sketch "Continue adjuster bore" plane through (0, 0, 51.9) normal (0, 0, 1) x axis (1, 0, 0)
  circle C1 centre (12, -55) radius 2.2
extrude "Extrude20" cut sketch "Continue adjuster bore" along normal blind 5.2
work_plane "WorkPlane21" AlongDistance 51.9 ExtraOffset 0
sketch "Continue guide bore" plane through (0, 0, 51.9) normal (0, 0, 1) x axis (1, 0, 0)
  circle C1 centre (5, -55) radius 1.7
extrude "Extrude21" cut sketch "Continue guide bore" along normal blind 5.2
work_plane "WorkPlane22" AlongDistance 51.9 ExtraOffset 0
sketch "Continue guide bore (1)" plane through (0, 0, 51.9) normal (0, 0, 1) x axis (1, 0, 0)
  circle C1 centre (19, -55) radius 1.7
extrude "Extrude22" cut sketch "Continue guide bore (1)" along normal blind 5.2
work_plane "WorkPlane23" AlongDistance -24.1 ExtraOffset 0
sketch "Preserve cam sweep clearance" plane through (-24.1, 0, 0) normal (1, 0, 0) x axis (0, 0, -1)
  circle C1 centre (-65, 0) radius 51
extrude "Extrude23" cut sketch "Preserve cam sweep clearance" along normal blind 48.2
work_plane "WorkPlane1" AlongDistance -23.85 ExtraOffset 0
sketch "Controlled rotor axial clearance" plane through (-23.85, 0, 0) normal (1, 0, 0) x axis (0, 0, -1)
  circle C1 centre (-65, 0) radius 10
extrude "Extrude1" new body sketch "Controlled rotor axial clearance" along normal blind 16.85 bodies "P23 Left rotor thrust spacer"
work_plane "WorkPlane2" AlongDistance -23.95 ExtraOffset 0
sketch "Free spacer bore" plane through (-23.95, 0, 0) normal (1, 0, 0) x axis (0, 0, -1)
  circle C1 centre (-65, 0) radius 8.2
extrude "Extrude2" cut sketch "Free spacer bore" along normal blind 17.05
work_plane "WorkPlane1" AlongDistance 7 ExtraOffset 0
sketch "Controlled rotor axial clearance" plane through (7, 0, 0) normal (1, 0, 0) x axis (0, 0, -1)
  circle C1 centre (-65, 0) radius 10
extrude "Extrude1" new body sketch "Controlled rotor axial clearance" along normal blind 16.85 bodies "P24 Right rotor thrust spacer"
work_plane "WorkPlane2" AlongDistance 6.9 ExtraOffset 0
sketch "Free spacer bore" plane through (6.9, 0, 0) normal (1, 0, 0) x axis (0, 0, -1)
  circle C1 centre (-65, 0) radius 8.2
extrude "Extrude2" cut sketch "Free spacer bore" along normal blind 17.05
work_plane "WorkPlane22" AlongDistance -76 ExtraOffset 0
sketch "Restore rail bolt clearance after hole filling" plane through (0, -76, 0) normal (0, 1, 0) x axis (1, 0, 0)
  circle C1 centre (-30, -45) radius 2.7
extrude "Extrude22" cut sketch "Restore rail bolt clearance after hole filling" along normal blind 22
work_plane "WorkPlane23" AlongDistance 54 ExtraOffset 0
sketch "Restore rail bolt clearance after hole filling (1)" plane through (0, 54, 0) normal (0, 1, 0) x axis (1, 0, 0)
  circle C1 centre (-30, -45) radius 2.7
work_plane "WorkPlane24" AlongDistance -55 ExtraOffset 0
sketch "Restore rail head access after hole filling" plane through (0, -55, 0) normal (0, 1, 0) x axis (1, 0, 0)
  circle C1 centre (-30, -45) radius 5.3
extrude "Extrude24" cut sketch "Restore rail head access after hole filling" along normal blind 12
work_plane "WorkPlane25" AlongDistance 43 ExtraOffset 0
sketch "Restore rail head access after hole filling (1)" plane through (0, 43, 0) normal (0, 1, 0) x axis (1, 0, 0)
  circle C1 centre (-30, -45) radius 5.3
work_plane "WorkPlane21" AlongDistance -76 ExtraOffset 0
sketch "Restore rail bolt clearance after hole filling" plane through (0, -76, 0) normal (0, 1, 0) x axis (1, 0, 0)
  circle C1 centre (30, -45) radius 2.7
extrude "Extrude21" cut sketch "Restore rail bolt clearance after hole filling" along normal blind 22
work_plane "WorkPlane22" AlongDistance 54 ExtraOffset 0
sketch "Restore rail bolt clearance after hole filling (1)" plane through (0, 54, 0) normal (0, 1, 0) x axis (1, 0, 0)
  circle C1 centre (30, -45) radius 2.7
work_plane "WorkPlane23" AlongDistance -55 ExtraOffset 0
sketch "Restore rail head access after hole filling" plane through (0, -55, 0) normal (0, 1, 0) x axis (1, 0, 0)
  circle C1 centre (30, -45) radius 5.3
extrude "Extrude23" cut sketch "Restore rail head access after hole filling" along normal blind 12
work_plane "WorkPlane24" AlongDistance 43 ExtraOffset 0
sketch "Restore rail head access after hole filling (1)" plane through (0, 43, 0) normal (0, 1, 0) x axis (1, 0, 0)
  circle C1 centre (30, -45) radius 5.3
work_plane "WorkPlane14" AlongDistance -18.1 ExtraOffset 0
sketch "Stop lug clearance for concentric thrust spacer" plane through (-18.1, 0, 0) normal (1, 0, 0) x axis (0, 0, -1)
  circle C1 centre (-65, 0) radius 10.2
extrude "Extrude14" cut sketch "Stop lug clearance for concentric thrust spacer" along normal blind 11
work_plane "WorkPlane15" AlongDistance -18.1 ExtraOffset 0
sketch "Complete stop lug relief to rotor face" plane through (-18.1, 0, 0) normal (1, 0, 0) x axis (0, 0, -1)
  circle C1 centre (-65, 0) radius 10.2
extrude "Extrude15" cut sketch "Complete stop lug relief to rotor face" along normal blind 11.1
ground "Pin2"
ground "Pin3"
ground "Pin4"
ground "Pin5"
ground "Pin6"
ground "Pin11"
ground "Pin12"
ground "Pin48"
ground "Pin49"
work_plane "WorkPlane24" AlongDistance -24 ExtraOffset 0
sketch "Extra roof over relocated heat-set inserts" plane through (-24, 0, 0) normal (1, 0, 0) x axis (0, 0, -1)
  line L1 (-57, -44) -> (-57, -66)
  line L2 (-59, -44) -> (-57, -44)
  line L3 (-59, -66) -> (-59, -44)
  line L4 (-57, -66) -> (-59, -66)
extrude "Extrude24" add sketch "Extra roof over relocated heat-set inserts" along normal blind 48
work_plane "WorkPlane25" AlongDistance -24 ExtraOffset 0
sketch "Fill former insert location" plane through (-24, 0, 0) normal (1, 0, 0) x axis (0, 0, -1)
  circle C1 centre (-52, -59) radius 2.01
extrude "Extrude25" add sketch "Fill former insert location" along normal blind 8.7
work_plane "WorkPlane26" AlongDistance 15.3 ExtraOffset 0
sketch "Fill former insert location (1)" plane through (15.3, 0, 0) normal (1, 0, 0) x axis (0, 0, -1)
  circle C1 centre (-52, -59) radius 2.01
extrude "Extrude26" add sketch "Fill former insert location (1)" along normal blind 8.7
work_plane "WorkPlane26" AlongDistance -36 ExtraOffset 0
sketch "Fill former plate mounting hole" plane through (-36, 0, 0) normal (1, 0, 0) x axis (0, 0, -1)
  circle C1 centre (-52, -59) radius 1.71
extrude "Extrude26" add sketch "Fill former plate mounting hole" along normal blind 12
work_plane "WorkPlane25" AlongDistance 24 ExtraOffset 0
sketch "Fill former plate mounting hole" plane through (24, 0, 0) normal (1, 0, 0) x axis (0, 0, -1)
  circle C1 centre (-52, -59) radius 1.71
extrude "Extrude25" add sketch "Fill former plate mounting hole" along normal blind 12
work_plane "WorkPlane27" AlongDistance -24 ExtraOffset 0
sketch "Fill former insert location (2)" plane through (-24, 0, 0) normal (1, 0, 0) x axis (0, 0, -1)
  circle C1 centre (-52, -51) radius 2.01
extrude "Extrude27" add sketch "Fill former insert location (2)" along normal blind 8.7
